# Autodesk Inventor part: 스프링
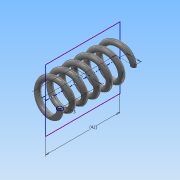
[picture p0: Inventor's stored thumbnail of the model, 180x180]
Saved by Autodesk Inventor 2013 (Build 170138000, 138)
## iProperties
Created: 2015-12
Part Number: 스프링
Material: 강철, 탄소
Document SubType Name: Modeling
Designer: Administrator
Density: 7.87 g/cm^3
Mass: 16.5341 g
Surface Area: 28.4696 cm^2
Volume: 2.1009 cm^3
Author: Administrator
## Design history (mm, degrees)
sketch "스케치1"
  geometry: L1 (0, 0)-(0, 42); L2 (0, 42)-(8, 42); C1 r 1.5 at (8, 0)
  constraints: 4 end point, 1 centre point, 1 horizontal alignment, 1 perpendicular, 1 vertical
  dimensions: "d0" = 42 distance of L1.start L1.end (derived); "d1" = 3 diameter of C1; "d2" = 16 diameter of C1.centre L1; "d3" = 8 distance of L1.end L2.end
feature "코일1" sketch "스케치1" pitch "d4" = 10; turns "d6" = 6; dims "d5" = 42 (= d0), "d7" = 0, angle "d8" = 90 deg, angle "d9" = 90 deg, "d10" = 0, "d11" = 0
sketch "스케치2"
  geometry: L1 (0, -17.6)-(42, -17.6); L2 (42, -17.6)-(42, 17.6); L3 (42, 17.6)-(0, 17.6); L4 (0, 17.6)-(0, -17.6); 2 further points
  constraints: 8 end point, 2 parallel, 1 coincident, 1 horizontal, 1 midpoint, 1 perpendicular
  dimensions: "d12" = 42 distance of L1.start L1.end (derived)
extrude "돌출1" sketch "스케치2" stored distance "d14" = 50; taper "d15" = 0 deg
node "솔리드1"
